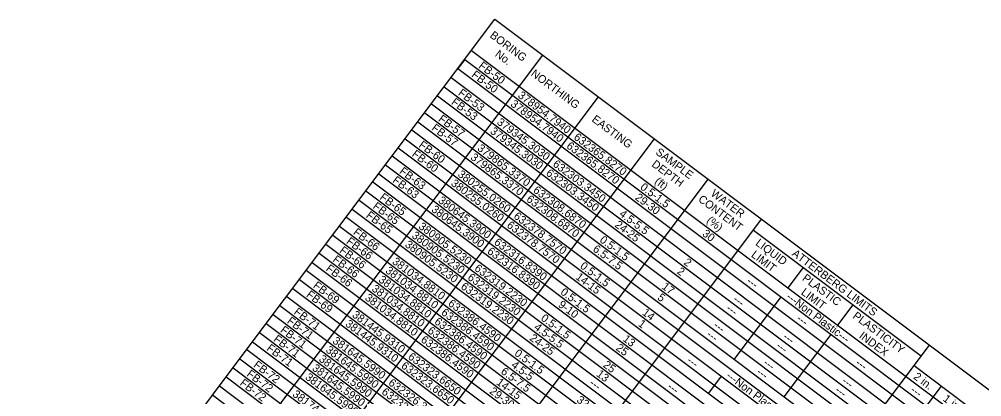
# Model space of a CAD drawing. Extents: x 627484.2 to 627514.4, y 367972.1 to 367996.9.
# Drawn here: x 627484.2 to 627490.82, y 367994.31 to 367996.91 of the extents above; entities that cross this region are included whole.
import ezdxf

# ---------------------------------------------------------------- set-up
doc = ezdxf.new("R2010")
doc.units = 0
doc.layers.add('Default', color=7, linetype='Continuous')
doc.layers.add('R_Survey Control', color=7, linetype='Continuous')

msp = doc.modelspace()

# ---------------------------------------------------------------- linework, layer by layer
at = {"layer": 'Default'}
for p, q in [((627485.6645, 367994.5006), (627487.4706, 367996.9059)), ((627487.4706, 367996.9059), (627492.71, 367992.9716)), ((627485.9514, 367994.1999), (627487.7985, 367996.6597)), ((627487.3096, 367996.6915), (627492.549, 367992.7571)), ((627487.2628, 367996.6291), (627487.2159, 367996.5667)), ((627487.2628, 367996.6291), (627492.5022, 367992.6948)), ((627487.2159, 367996.5667), (627492.4553, 367992.6324)), ((627487.1691, 367996.5044), (627492.4085, 367992.57)), ((627487.1223, 367996.442), (627492.3617, 367992.5077)), ((627486.3352, 367993.9116), (627488.1823, 367996.3715)), ((627487.0344, 367996.325), (627492.2739, 367992.3907)), ((627487.0754, 367996.3796), (627492.3148, 367992.4453)), ((627486.9876, 367996.2627), (627492.227, 367992.3283)), ((627486.9408, 367996.2003), (627492.1802, 367992.266)), ((627486.8998, 367996.1457), (627492.1392, 367992.2114)), ((627486.719, 367993.6234), (627488.5661, 367996.0832)), ((627486.8529, 367996.0833), (627492.0924, 367992.149)), ((627486.8061, 367996.021), (627492.0455, 367992.0866)), ((627486.7651, 367995.9664), (627492.0045, 367992.0321)), ((627486.7183, 367995.904), (627491.9577, 367991.9697)), ((627486.6715, 367995.8416), (627491.9109, 367991.9073)), ((627487.0894, 367993.3453), (627488.9365, 367995.8052)), ((627486.5836, 367995.7247), (627491.8231, 367991.7904)), ((627486.6305, 367995.7871), (627491.8699, 367991.8527)), ((627486.5368, 367995.6623), (627491.7762, 367991.728)), ((627486.49, 367995.5999), (627491.7294, 367991.6656)), ((627486.449, 367995.5454), (627491.6884, 367991.611)), ((627487.4558, 367993.0702), (627489.3029, 367995.53)), ((627486.4021, 367995.483), (627491.6416, 367991.5487)), ((627486.3553, 367995.4206), (627491.5947, 367991.4863)), ((627489.2473, 367995.4559), (627490.4012, 367994.5894)), ((627486.3085, 367995.3583), (627491.5479, 367991.4239)), ((627486.2616, 367995.2959), (627491.5011, 367991.3616)), ((627486.2148, 367995.2335), (627491.4542, 367991.2992)), ((627489.485, 367995.058), (627489.5903, 367995.1983)), ((627486.1738, 367995.1789), (627491.4132, 367991.2446)), ((627486.127, 367995.1166), (627491.3664, 367991.1822)), ((627486.0392, 367994.9996), (627491.2786, 367991.0653)), ((627486.0801, 367995.0542), (627491.3196, 367991.1199)), ((627489.1161, 367994.5668), (627489.4381, 367994.9956)), ((627485.9923, 367994.9372), (627491.2317, 367991.0029)), ((627489.828, 367994.8004), (627489.9334, 367994.9407)), ((627485.9455, 367994.8749), (627491.1849, 367990.9405)), ((627485.8987, 367994.8125), (627491.1381, 367990.8782)), ((627485.8518, 367994.7501), (627491.0912, 367990.8158)), ((627489.4592, 367994.3092), (627489.7812, 367994.738)), ((627485.805, 367994.6877), (627491.0444, 367990.7534)), ((627487.187, 367990.3091), (627490.4568, 367994.6635)), ((627485.764, 367994.6332), (627491.0034, 367990.6988)), ((627485.7172, 367994.5708), (627490.9566, 367990.6365)), ((627484.2008, 367992.5515), (627485.6645, 367994.5006)), ((627485.6703, 367994.5084), (627490.9097, 367990.5741)), ((627490.3514, 367994.5232), (627491.9419, 367993.3289)), ((627485.6235, 367994.4461), (627490.8629, 367990.5117)), ((627488.9405, 367994.3329), (627489.0283, 367994.4498)), ((627485.5767, 367994.3837), (627490.8161, 367990.4494)), ((627488.7968, 367992.0632), (627490.5385, 367994.3827)), ((627485.5298, 367994.3213), (627490.7692, 367990.387))]:
    msp.add_line(p, q, dxfattribs=at)
at = {"layer": 'R_Survey Control'}
msp.add_line((627488.2348, 367996.3321), (627488.2348, 367996.3321), dxfattribs=at)

# ---------------------------------------------------------------- texts
at = {"layer": 'Default'}
for s, p in [('BORING', (627487.4307, 367996.7854)), ('No.', (627487.4663, 367996.6555)), ('FB-50', (627487.3535, 367996.5754)), ('FB-50', (627487.3049, 367996.5143)), ('NORTHING', (627487.713, 367996.5218)), ('FB-53', (627487.2128, 367996.3884)), ('378954.7940', (627487.6235, 367996.3726)), ('FB-53', (627487.1659, 367996.326)), ('378954.7940', (627487.5732, 367996.3128)), ('FB-57', (627487.03, 367996.1476)), ('FB-57', (627487.0769, 367996.21)), ('379345.3030', (627487.4795, 367996.1881)), ('EASTING', (627488.1311, 367996.2078)), ('379345.3030', (627487.4327, 367996.1257)), ('632365.8270', (627488.0074, 367996.0844)), ('FB-60', (627486.9419, 367996.0309)), ('632365.8270', (627487.957, 367996.0246)), ('FB-60', (627486.8951, 367995.9685)), ('379865.3370', (627487.3449, 367996.0088)), ('SAMPLE', (627488.5698, 367995.9816)), ('379865.3370', (627487.298, 367995.9464)), ('632303.3450', (627487.8633, 367995.8999)), ('DEPTH', (627488.5428, 367995.8987)), ('FB-63', (627486.8088, 367995.8504)), ('380255.0260', (627487.2102, 367995.8295)), ('632303.3450', (627487.8165, 367995.8375)), ('FB-63', (627486.762, 367995.7881)), ('380255.0260', (627487.1634, 367995.7671)), ('(ft)', (627488.5627, 367995.7806)), ('632308.6870', (627487.7287, 367995.7206)), ('0.5-1.5', (627488.464, 367995.7415)), ('WATER', (627488.949, 367995.6968)), ('FB-65', (627486.6736, 367995.6715)), ('380645.3900', (627487.0755, 367995.6501)), ('632308.6870', (627487.6819, 367995.6582)), ('29-30', (627488.4289, 367995.6703)), ('CONTENT', (627488.863, 367995.6583)), ('FB-65', (627486.6268, 367995.6092)), ('380645.3900', (627487.0287, 367995.5878)), ('FB-65', (627486.5799, 367995.5468)), ('632378.7570', (627487.594, 367995.5412)), ('4.5-5.5', (627488.32, 367995.557)), ('(%)', (627488.9202, 367995.5121)), ('FB-66', (627486.4912, 367995.4305)), ('380905.5230', (627486.9409, 367995.4708)), ('632378.7570', (627487.5472, 367995.4789)), ('24-25', (627488.2894, 367995.4824)), ('30', (627488.8909, 367995.4209)), ('FB-66', (627486.4444, 367995.3681)), ('380905.5230', (627486.8941, 367995.4084)), ('632316.8390', (627487.4594, 367995.3619)), ('0.5-1.5', (627488.1853, 367995.3777)), ('LIQUID', (627489.2565, 367995.3565)), ('FB-66', (627486.3975, 367995.3058)), ('380905.5230', (627486.8472, 367995.3461)), ('632316.8390', (627487.4125, 367995.2995)), ('6.5-7.5', (627488.1385, 367995.3153)), ('FB-66', (627486.3507, 367995.2434)), ('381034.8810', (627486.7594, 367995.2291)), ('2', (627488.7633, 367995.2241)), ('LIMIT', (627489.2266, 367995.2758)), ('ATTERBERG LIMITS', (627489.507, 367995.2844)), ('FB-66', (627486.3039, 367995.181)), ('381034.8810', (627486.7126, 367995.1667)), ('632319.2230', (627487.3247, 367995.1826)), ('0.5-1.5', (627488.0507, 367995.1984)), ('2', (627488.7165, 367995.1617)), ('381034.8810', (627486.6657, 367995.1044)), ('632319.2230', (627487.2779, 367995.1202)), ('14-15', (627488.02, 367995.1238)), ('PLASTIC', (627489.5782, 367995.1149)), ('FB-69', (627486.2162, 367995.064)), ('381034.8810', (627486.6189, 367995.042)), ('632319.2230', (627487.2311, 367995.0578)), ('17', (627488.6126, 367995.0569)), ('---', (627489.1955, 367995.0946)), ('FB-69', (627486.1693, 367995.0016)), ('381034.8810', (627486.5721, 367994.9796)), ('0.5-1.5', (627487.916, 367995.019)), ('5', (627488.5826, 367994.9818)), ('---Non Plastic---', (627489.4681, 367994.9875)), ('LIMIT', (627489.5696, 367995.0182)), ('632386.4590', (627487.1432, 367994.9409)), ('9-10', (627487.9007, 367994.933)), ('---', (627489.1018, 367994.9699)), ('FB-71', (627486.0841, 367994.8827)), ('381445.9310', (627486.4842, 367994.8627)), ('632386.4590', (627487.0964, 367994.8785)), ('0.5-1.5', (627487.7813, 367994.8397)), ('14', (627488.4776, 367994.8778)), ('---', (627489.055, 367994.9075)), ('PLASTICITY', (627489.9244, 367994.8549)), ('FB-71', (627485.9905, 367994.7579)), ('FB-71', (627486.0373, 367994.8203)), ('381445.9310', (627486.4374, 367994.8003)), ('632386.4590', (627487.0496, 367994.8161)), ('4.5-5.5', (627487.7345, 367994.7773)), ('1', (627488.4498, 367994.8011)), ('---', (627488.9672, 367994.7906)), ('---', (627489.5385, 367994.837)), ('FB-71', (627485.9436, 367994.6956)), ('632386.4590', (627487.0027, 367994.7538)), ('24-25', (627487.7039, 367994.7028)), ('13', (627488.3445, 367994.6973)), ('---', (627488.9203, 367994.7282)), ('---', (627489.4449, 367994.7123)), ('INDEX', (627489.9687, 367994.7185)), ('FB-71', (627485.8968, 367994.6332)), ('381645.5990', (627486.3496, 367994.6834)), ('632386.4590', (627486.9559, 367994.6914)), ('25', (627488.2971, 367994.6353)), ('---', (627489.398, 367994.6499)), ('381645.5990', (627486.3027, 367994.621)), ('632323.6650', (627486.8681, 367994.5745)), ('0.5-1.5', (627487.5999, 367994.598)), ('FB-72', (627485.8063, 367994.5182)), ('381645.5990', (627486.2091, 367994.4962)), ('381645.5990', (627486.2559, 367994.5586)), ('632323.6650', (627486.8212, 367994.5121)), ('4.5-5', (627487.5774, 367994.5173)), ('25', (627488.2093, 367994.5184)), ('---', (627488.7857, 367994.5489)), ('---', (627489.3102, 367994.533)), ('---', (627489.944, 367994.5326)), ('FB-72', (627485.7595, 367994.4559)), ('381645.5990', (627486.1622, 367994.4339)), ('6.5-7.5', (627487.5062, 367994.4733)), ('13', (627488.163, 367994.4556)), ('---', (627489.2634, 367994.4706)), ('2 in.', (627490.3424, 367994.4376)), ('FB-72', (627485.7127, 367994.3935)), ('632326.3050', (627486.7334, 367994.3951)), ('14-15', (627487.4756, 367994.3987)), ('---', (627488.1148, 367994.3942)), ('---Non Plastic---', (627489.0548, 367994.4443)), ('---', (627489.8503, 367994.4079)), ('381744.7990', (627486.0744, 367994.3169)), ('632326.3050', (627486.6866, 367994.3328)), ('29-30', (627487.4278, 367994.3371)), ('---', (627488.651, 367994.3696)), ('---', (627489.8034, 367994.3455)), ('---', (627490.3217, 367994.3465)), ('32', (627488.027, 367994.2773)), ('1 in.', (627490.5451, 367994.2854))]:
    msp.add_text(s, height=0.055, rotation=323.09678, dxfattribs=at).set_placement(p)

doc.saveas('drawing.dxf')
